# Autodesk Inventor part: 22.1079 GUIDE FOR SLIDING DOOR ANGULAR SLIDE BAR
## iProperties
Created: 2007-05
Part Number: 22.1079 GUIDE FOR SLIDING DOOR ANGULAR SLIDE BAR
Material: UHMW, Black
Document SubType Name: Modeling
Designer: Andy Moles
Density: 0.94 g/cm^3
Mass: 10.2648 g
Surface Area: 49.4135 cm^2
Volume: 10.92 cm^3
Author: Andy Moles
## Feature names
1. Extrusion1
2. Extrusion2
3. Extrusion3
